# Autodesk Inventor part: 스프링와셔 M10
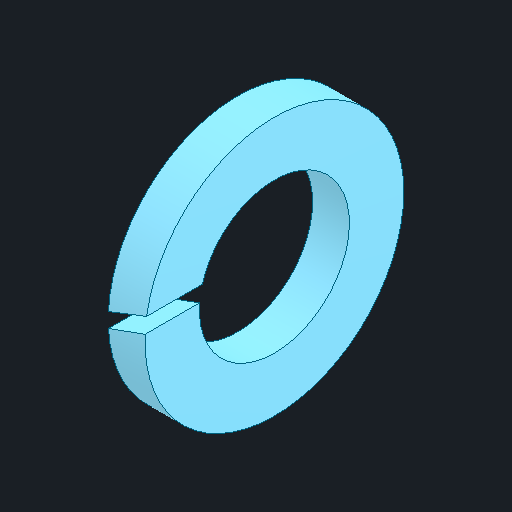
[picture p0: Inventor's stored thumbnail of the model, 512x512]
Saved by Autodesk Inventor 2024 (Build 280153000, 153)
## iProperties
Created: 2025-02
Part Number: 스프링와셔 M10
Material: 강철, 연강
Description: 스프링 잠금 와셔
Document SubType Name: Modeling
Designer: kh_501
Density: 7.85 g/cm^3
Appearance: 기본값
Author: jhkim
Sending System: Autodesk Inventor 2025
Preprocessor: ST-DEVELOPER v20
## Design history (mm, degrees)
node "스프링와셔 M101"
node "솔리드1"
body "Solid1"
